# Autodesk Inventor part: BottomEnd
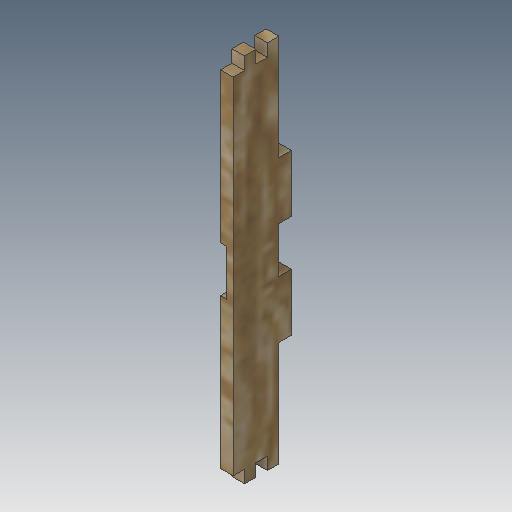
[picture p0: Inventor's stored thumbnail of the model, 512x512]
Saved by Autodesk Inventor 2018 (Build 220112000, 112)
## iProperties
Created: 2018-05
Part Number: BottomEnd
Material: Generic
Document SubType Name: Modeling
Designer: arivu
Density: 1 g/cm^3
Appearance: Default
Author: arivu
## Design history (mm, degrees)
derived "WaterTank.ipt"
feature "Solid32::WaterTank.ipt" dims "d0" = 10
tag "TaggingFeature1"
body "Solid1"
